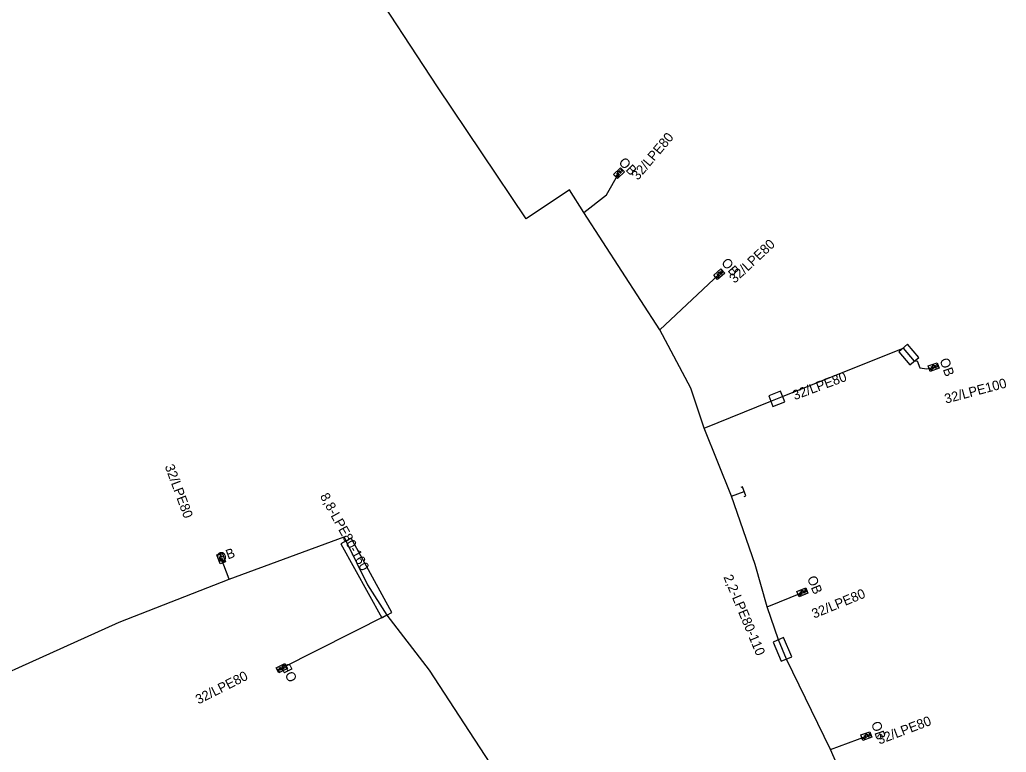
# Model space of a CAD drawing. Extents: x -762509 to -761250, y -1153000 to -1152256.
# Drawn here: x -761661 to -761558.4, y -1152486 to -1152409.7 of the extents above; entities that cross this region are included whole.
import ezdxf

# ---------------------------------------------------------------- set-up
doc = ezdxf.new("R2010")
doc.units = 0
for name, color, linetype in [('Vrstva 21', 7, 'Continuous'), ('Vrstva 29', 7, 'Continuous'), ('Vrstva 31', 7, 'Continuous'), ('Vrstva 32', 7, 'Continuous'), ('Vrstva 33', 7, 'Continuous')]:
    doc.layers.add(name, color=color, linetype=linetype)

msp = doc.modelspace()

# ---------------------------------------------------------------- linework, layer by layer
at = {"layer": 'Vrstva 21'}
for points in [[(-761573.13, -1152512), (-761567.78, -1152509.12), (-761568.47, -1152506.37), (-761575.11, -1152489.35), (-761576.69, -1152485.72), (-761581.29, -1152476.29), (-761582.13, -1152474.29), (-761583.3, -1152470.86), (-761584.55, -1152466.45), (-761587.02, -1152459.35), (-761589.85, -1152452.27), (-761591.23, -1152448.11), (-761594.46, -1152442.02), (-761602.36, -1152429.8), (-761603.86, -1152427.44), (-761608.36, -1152430.48), (-761617.59, -1152416.73), (-761625.33, -1152404.89)], [(-761672.69, -1152482.38), (-761650.69, -1152472.45), (-761639.27, -1152467.98), (-761627.28, -1152463.58), (-761627.11, -1152464), (-761624.85, -1152468.58), (-761622.86, -1152471.73), (-761618.45, -1152477.46), (-761609.01, -1152491.92), (-761604.85, -1152497.81), (-761601.61, -1152501.48), (-761599.32, -1152504.35), (-761597.57, -1152506.03), (-761596.02, -1152506.9), (-761589.78, -1152509.1), (-761582.63, -1152510.73), (-761579.95, -1152510.84), (-761577.86, -1152510.36), (-761574.83, -1152508.85), (-761573.13, -1152512)]]:
    msp.add_lwpolyline(points, dxfattribs=at)
at = {"layer": 'Vrstva 29'}
for points in [[(-761569.6, -1152444.31), (-761568.45, -1152445.67), (-761567.53, -1152444.89), (-761568.68, -1152443.53)], [(-761582.69, -1152450.01), (-761581.47, -1152449.52), (-761581.91, -1152448.4), (-761583.13, -1152448.89)], [(-761627.64, -1152464.29), (-761623.39, -1152472.02), (-761622.33, -1152471.44), (-761626.58, -1152463.71)], [(-761582.68, -1152474.52), (-761581.84, -1152476.52), (-761580.74, -1152476.06), (-761581.58, -1152474.06)]]:
    msp.add_lwpolyline(points, close=True, dxfattribs=at)
at = {"layer": 'Vrstva 31'}
for points in [[(-761602.36, -1152429.8), (-761599.99, -1152427.96), (-761598.71, -1152425.71)], [(-761594.46, -1152442.02), (-761588.28, -1152436.23)], [(-761589.85, -1152452.27), (-761582.91, -1152449.45), (-761581.69, -1152448.96), (-761569.14, -1152443.92), (-761567.99, -1152445.28), (-761567.7, -1152445.24)], [(-761567.7, -1152445.24), (-761567.41, -1152445.99), (-761566.68, -1152446.09), (-761565.97, -1152445.9)], [(-761587.02, -1152459.35), (-761585.68, -1152458.84)], [(-761639.27, -1152467.98), (-761640.08, -1152465.8)], [(-761583.3, -1152470.86), (-761579.63, -1152469.35)], [(-761622.86, -1152471.73), (-761633.77, -1152477.24)], [(-761576.69, -1152485.72), (-761572.97, -1152484.31)]]:
    msp.add_lwpolyline(points, dxfattribs=at)
at = {"layer": 'Vrstva 32'}
for p, q in [((-761598.976, -1152425.725), (-761598.731, -1152425.975)), ((-761598.691, -1152425.445), (-761598.446, -1152425.695)), ((-761598.418, -1152425.437), (-761598.561, -1152425.577)), ((-761598.302, -1152425.555), (-761598.547, -1152425.305)), ((-761588.545, -1152436.227), (-761588.317, -1152436.493)), ((-761588.242, -1152435.967), (-761588.015, -1152436.233)), ((-761587.969, -1152435.977), (-761588.122, -1152436.108)), ((-761587.862, -1152436.102), (-761588.09, -1152435.837)), ((-761566.217, -1152445.801), (-761566.101, -1152446.131)), ((-761565.84, -1152445.669), (-761565.725, -1152446)), ((-761565.589, -1152445.778), (-761565.779, -1152445.844)), ((-761565.535, -1152445.933), (-761565.65, -1152445.603)), ((-761640.055, -1152465.364), (-761640.383, -1152465.486)), ((-761640.313, -1152465.674), (-761639.985, -1152465.552)), ((-761640.21, -1152465.421), (-761640.14, -1152465.61)), ((-761640.175, -1152466.048), (-761639.846, -1152465.926)), ((-761579.512, -1152469.113), (-761579.379, -1152469.436)), ((-761579.194, -1152469.36), (-761579.326, -1152469.036)), ((-761579.881, -1152469.264), (-761579.749, -1152469.588)), ((-761579.256, -1152469.207), (-761579.442, -1152469.284)), ((-761634.206, -1152477.264), (-761634.048, -1152477.576)), ((-761634.132, -1152477.411), (-761633.952, -1152477.32)), ((-761633.869, -1152477.486), (-761634.027, -1152477.173)), ((-761633.513, -1152477.306), (-761633.671, -1152476.993)), ((-761573.217, -1152484.211), (-761573.101, -1152484.541)), ((-761572.84, -1152484.079), (-761572.725, -1152484.41)), ((-761572.589, -1152484.188), (-761572.779, -1152484.254)), ((-761572.535, -1152484.343), (-761572.65, -1152484.013))]:
    msp.add_line(p, q, dxfattribs=at)
for points in [[(-761598.143, -1152425.574), (-761598.857, -1152426.274), (-761599.277, -1152425.845), (-761598.563, -1152425.145), (-761598.143, -1152425.574)], [(-761598.731, -1152425.975), (-761598.823, -1152426.066), (-761598.865, -1152426.083), (-761598.887, -1152426.082), (-761598.92, -1152426.068), (-761598.955, -1152426.032), (-761598.968, -1152425.999), (-761598.969, -1152425.977), (-761598.951, -1152425.936), (-761598.858, -1152425.845)], [(-761598.516, -1152425.765), (-761598.692, -1152425.585), (-761598.736, -1152425.56), (-761598.781, -1152425.558), (-761598.823, -1152425.575), (-761598.844, -1152425.596), (-761598.862, -1152425.637), (-761598.86, -1152425.681), (-761598.836, -1152425.726), (-761598.66, -1152425.905)], [(-761587.705, -1152436.132), (-761588.464, -1152436.783), (-761588.854, -1152436.328), (-761588.095, -1152435.677), (-761587.705, -1152436.132)], [(-761588.09, -1152436.298), (-761588.253, -1152436.107), (-761588.296, -1152436.079), (-761588.341, -1152436.074), (-761588.384, -1152436.089), (-761588.406, -1152436.107), (-761588.426, -1152436.148), (-761588.427, -1152436.192), (-761588.406, -1152436.238), (-761588.242, -1152436.428)], [(-761588.317, -1152436.493), (-761588.416, -1152436.577), (-761588.459, -1152436.592), (-761588.481, -1152436.59), (-761588.513, -1152436.574), (-761588.546, -1152436.536), (-761588.556, -1152436.502), (-761588.555, -1152436.48), (-761588.535, -1152436.439), (-761588.436, -1152436.355)], [(-761565.399, -1152446.018), (-761566.343, -1152446.348), (-761566.541, -1152445.782), (-761565.597, -1152445.452), (-761565.399, -1152446.018)], [(-761566.101, -1152446.131), (-761566.224, -1152446.174), (-761566.269, -1152446.172), (-761566.289, -1152446.162), (-761566.313, -1152446.135), (-761566.329, -1152446.088), (-761566.327, -1152446.052), (-761566.318, -1152446.032), (-761566.284, -1152446.002), (-761566.161, -1152445.96)], [(-761565.818, -1152446.032), (-761565.901, -1152445.795), (-761565.93, -1152445.754), (-761565.97, -1152445.733), (-761566.016, -1152445.731), (-761566.043, -1152445.74), (-761566.077, -1152445.77), (-761566.094, -1152445.811), (-761566.091, -1152445.862), (-761566.008, -1152446.099)], [(-761639.973, -1152465.227), (-761639.625, -1152466.164), (-761640.187, -1152466.373), (-761640.535, -1152465.436), (-761639.973, -1152465.227)], [(-761639.951, -1152465.645), (-761640.186, -1152465.733), (-761640.227, -1152465.763), (-761640.247, -1152465.803), (-761640.249, -1152465.849), (-761640.239, -1152465.876), (-761640.208, -1152465.909), (-761640.167, -1152465.925), (-761640.116, -1152465.921), (-761639.881, -1152465.834)], [(-761639.846, -1152465.926), (-761639.801, -1152466.048), (-761639.802, -1152466.094), (-761639.812, -1152466.113), (-761639.838, -1152466.138), (-761639.885, -1152466.155), (-761639.921, -1152466.154), (-761639.941, -1152466.145), (-761639.972, -1152466.112), (-761640.017, -1152465.99)], [(-761579.054, -1152469.438), (-761579.979, -1152469.818), (-761580.206, -1152469.263), (-761579.281, -1152468.883), (-761579.054, -1152469.438)], [(-761579.749, -1152469.588), (-761579.869, -1152469.637), (-761579.914, -1152469.638), (-761579.934, -1152469.628), (-761579.96, -1152469.603), (-761579.979, -1152469.557), (-761579.978, -1152469.521), (-761579.97, -1152469.501), (-761579.938, -1152469.469), (-761579.818, -1152469.42)], [(-761579.471, -1152469.474), (-761579.566, -1152469.242), (-761579.598, -1152469.202), (-761579.639, -1152469.183), (-761579.684, -1152469.183), (-761579.711, -1152469.194), (-761579.744, -1152469.226), (-761579.758, -1152469.268), (-761579.752, -1152469.318), (-761579.657, -1152469.55)], [(-761634.352, -1152477.197), (-761633.459, -1152476.746), (-761633.189, -1152477.282), (-761634.081, -1152477.733), (-761634.352, -1152477.197)], [(-761633.938, -1152477.128), (-761633.825, -1152477.353), (-761633.791, -1152477.39), (-761633.748, -1152477.405), (-761633.703, -1152477.402), (-761633.677, -1152477.389), (-761633.647, -1152477.354), (-761633.636, -1152477.312), (-761633.646, -1152477.262), (-761633.759, -1152477.038)], [(-761633.671, -1152476.993), (-761633.555, -1152476.935), (-761633.509, -1152476.931), (-761633.489, -1152476.938), (-761633.461, -1152476.962), (-761633.439, -1152477.006), (-761633.436, -1152477.042), (-761633.443, -1152477.063), (-761633.472, -1152477.097), (-761633.589, -1152477.156)], [(-761572.399, -1152484.428), (-761573.343, -1152484.758), (-761573.541, -1152484.192), (-761572.597, -1152483.862), (-761572.399, -1152484.428)], [(-761573.101, -1152484.541), (-761573.224, -1152484.584), (-761573.269, -1152484.582), (-761573.289, -1152484.572), (-761573.313, -1152484.545), (-761573.329, -1152484.498), (-761573.327, -1152484.462), (-761573.318, -1152484.442), (-761573.284, -1152484.412), (-761573.161, -1152484.369)], [(-761572.818, -1152484.442), (-761572.901, -1152484.205), (-761572.93, -1152484.164), (-761572.97, -1152484.143), (-761573.016, -1152484.141), (-761573.043, -1152484.15), (-761573.077, -1152484.18), (-761573.094, -1152484.221), (-761573.091, -1152484.272), (-761573.008, -1152484.509)]]:
    msp.add_lwpolyline(points, dxfattribs=at)
at = {"layer": 'Vrstva 33'}
msp.add_lwpolyline([(-761585.69, -1152459.378), (-761585.503, -1152459.307), (-761585.856, -1152458.372), (-761586.043, -1152458.443)], dxfattribs=at)

# ---------------------------------------------------------------- texts
at = {"layer": 'Vrstva 29'}
for s, rotation, p in [('8,8-LPE80-160', 298.80226, (-761629.84, -1152459.34)), ('2,2-LPE80-110', 292.78241, (-761587.86, -1152467.75))]:
    msp.add_text(s, height=1, rotation=rotation, dxfattribs=at).set_placement(p)
at = {"layer": 'Vrstva 31'}
for s, rotation, p in [('32/LPE80', 49.92359, (-761596.74, -1152426.51)), ('32/LPE80', 49.92359, (-761596.74, -1152426.51)), ('32/LPE80', 43.13388, (-761586.68, -1152437.24)), ('32/LPE80', 43.13388, (-761586.68, -1152437.24)), ('32/LPE80', 20.44819, (-761580.43, -1152449.35)), ('32/LPE80', 20.44819, (-761580.43, -1152449.35)), ('32/LPE100', 14.93142, (-761564.7, -1152449.71)), ('32/LPE100', 14.93142, (-761564.7, -1152449.71)), ('32/LPE80', 290.38303, (-761645.97, -1152456.23)), ('32/LPE80', 290.38303, (-761645.97, -1152456.23)), ('32/LPE80', 22.36443, (-761578.41, -1152472.09)), ('32/LPE80', 22.36443, (-761578.41, -1152472.09)), ('32/LPE80', 26.79566, (-761642.45, -1152481.03)), ('32/LPE80', 26.79566, (-761642.45, -1152481.03)), ('32/LPE80', 20.75833, (-761571.62, -1152485.2)), ('32/LPE80', 20.75833, (-761571.62, -1152485.2))]:
    msp.add_text(s, height=1, rotation=rotation, dxfattribs=at).set_placement(p)
at = {"layer": 'Vrstva 32'}
for rotation, p in [(314.42676, (-761598.81, -1152424.66)), (314.42676, (-761598.81, -1152424.66)), (310.61667, (-761588.13, -1152435.07)), (310.61667, (-761588.13, -1152435.07)), (289.26935, (-761565.37, -1152445.16)), (289.26935, (-761565.37, -1152445.16)), (20.38303, (-761640.36, -1152466.3)), (20.38303, (-761640.36, -1152466.3)), (292.32383, (-761579.16, -1152467.87)), (292.32383, (-761579.16, -1152467.87)), (116.79566, (-761632.14, -1152478.37)), (116.79566, (-761632.14, -1152478.37)), (289.26337, (-761572.5, -1152482.98)), (289.26337, (-761572.5, -1152482.98))]:
    msp.add_text('OB', height=1, rotation=rotation, dxfattribs=at).set_placement(p)

doc.saveas('drawing.dxf')
